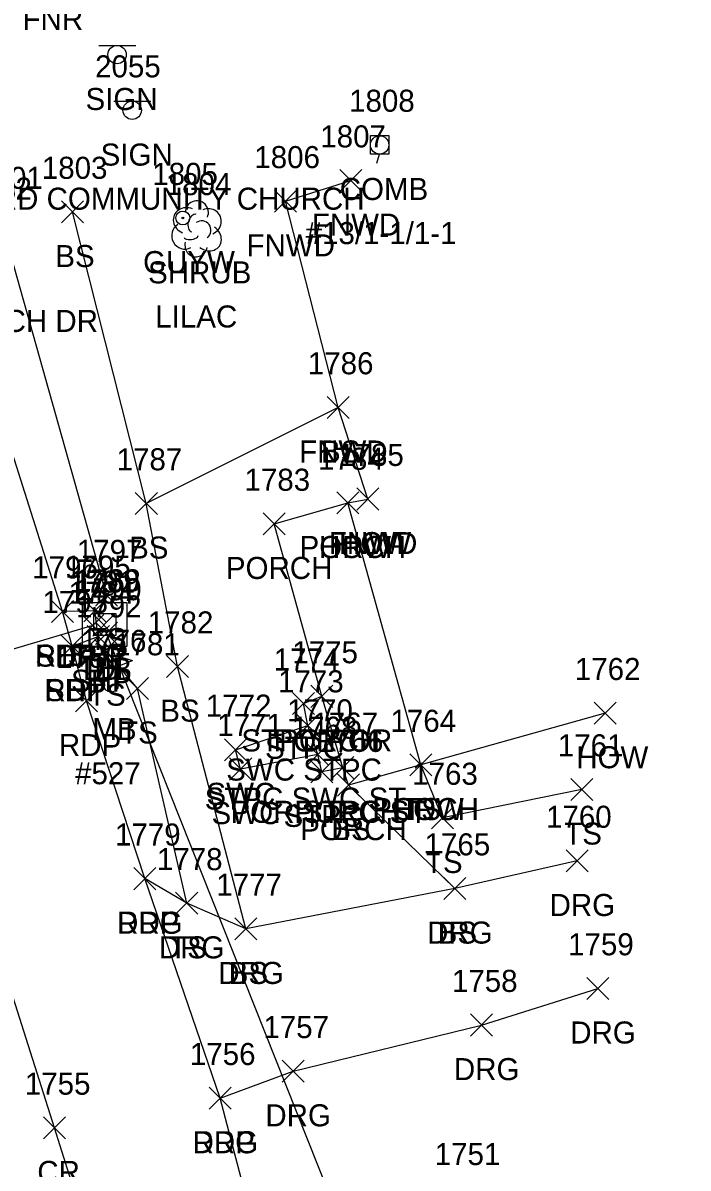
# Model space of a CAD drawing. Extents: x 1620157 to 1620595, y 115111 to 117885.
# Drawn here: x 1620291.9 to 1620352.1, y 115548.1 to 115651.9 of the extents above; entities that cross this region are included whole.
import ezdxf

# ---------------------------------------------------------------- set-up
doc = ezdxf.new("R2010")
doc.units = 0
for name, color, linetype in [('D_A', 7, 'Continuous'), ('D_I', 7, 'Continuous'), ('D_TIC', 7, 'Continuous'), ('DCP', 7, 'Continuous'), ('DS', 7, 'Continuous'), ('L_A', 7, 'Continuous'), ('L_C', 7, 'Continuous'), ('L_I', 7, 'Continuous'), ('L_TIC', 7, 'Continuous'), ('LBC', 7, 'Continuous'), ('LBF', 7, 'Continuous'), ('LELB', 7, 'Continuous'), ('LFNC', 7, 'Continuous'), ('LMB', 7, 'Continuous'), ('LSH', 7, 'Continuous'), ('P_A', 7, 'Continuous'), ('P_I', 7, 'Continuous'), ('P_TIC', 7, 'Continuous'), ('PET', 7, 'Continuous'), ('PRC', 7, 'Continuous'), ('PSP', 7, 'Continuous'), ('R_A', 7, 'Continuous'), ('R_I', 7, 'Continuous'), ('R_TIC', 7, 'Continuous'), ('RDG', 7, 'Continuous'), ('RSW', 7, 'Continuous'), ('S_A', 7, 'Continuous'), ('S_C', 7, 'Continuous'), ('S_I', 7, 'Continuous'), ('SSGN', 7, 'Continuous'), ('U_A', 7, 'Continuous'), ('U_C', 7, 'Continuous'), ('U_I', 7, 'Continuous'), ('UP', 7, 'Continuous'), ('UPGW', 7, 'Continuous')]:
    doc.layers.add(name, color=color, linetype=linetype)

msp = doc.modelspace()

# ---------------------------------------------------------------- linework, layer by layer
at = {"layer": 'D_TIC'}
for points in [[(1620297.2, 115596.27), (1620299.2, 115598.27)], [(1620299.2, 115596.27), (1620297.2, 115598.27)], [(1620298.19, 115596.33), (1620300.19, 115598.33)], [(1620300.19, 115596.33), (1620298.19, 115598.33)], [(1620298.44, 115595.57), (1620300.44, 115597.57)], [(1620300.44, 115595.57), (1620298.44, 115597.57)]]:
    msp.add_lwpolyline(points, dxfattribs=at)
at = {"layer": 'DCP'}
for points in [[(1620298.2, 115597.27), (1620266.48, 115587.84)], [(1620352.15, 115463.88), (1620299.44, 115596.57)]]:
    msp.add_lwpolyline(points, dxfattribs=at)
at = {"layer": 'DS'}
for p, q in [((1620297.27, 115599.38), (1620301.27, 115599.38)), ((1620297.27, 115595.38), (1620297.27, 115599.38)), ((1620301.27, 115599.38), (1620301.27, 115595.38)), ((1620298.27, 115596.38), (1620298.27, 115598.38)), ((1620298.27, 115598.38), (1620300.27, 115598.38)), ((1620300.27, 115598.38), (1620300.27, 115596.38)), ((1620299.28, 115597.38), (1620299.28, 115597.38)), ((1620299.28, 115597.38), (1620299.28, 115597.38)), ((1620300.27, 115596.38), (1620298.27, 115596.38)), ((1620301.27, 115595.38), (1620297.27, 115595.38))]:
    msp.add_line(p, q, dxfattribs=at)
at = {"layer": 'L_TIC'}
for points in [[(1620320.58, 115636.63), (1620322.58, 115638.63)], [(1620322.58, 115636.63), (1620320.58, 115638.63)], [(1620314.66, 115634.75), (1620316.66, 115636.75)], [(1620316.66, 115634.75), (1620314.66, 115636.75)], [(1620295.35, 115633.78), (1620297.35, 115635.78)], [(1620297.35, 115633.78), (1620295.35, 115635.78)], [(1620319.43, 115616.06), (1620321.43, 115618.06)], [(1620321.43, 115616.06), (1620319.43, 115618.06)], [(1620319.43, 115616.06), (1620321.43, 115618.06)], [(1620321.43, 115616.06), (1620319.43, 115618.06)], [(1620302.04, 115607.35), (1620304.04, 115609.35)], [(1620304.04, 115607.35), (1620302.04, 115609.35)], [(1620302.04, 115607.35), (1620304.04, 115609.35)], [(1620304.04, 115607.35), (1620302.04, 115609.35)], [(1620320.31, 115607.4), (1620322.31, 115609.4)], [(1620322.31, 115607.4), (1620320.31, 115609.4)], [(1620320.31, 115607.4), (1620322.31, 115609.4)], [(1620322.31, 115607.4), (1620320.31, 115609.4)], [(1620322.12, 115607.75), (1620324.12, 115609.75)], [(1620324.12, 115607.75), (1620322.12, 115609.75)], [(1620322.12, 115607.75), (1620324.12, 115609.75)], [(1620324.12, 115607.75), (1620322.12, 115609.75)], [(1620313.63, 115605.5), (1620315.63, 115607.5)], [(1620315.63, 115605.5), (1620313.63, 115607.5)], [(1620298.44, 115599.05), (1620300.44, 115601.05)], [(1620300.44, 115599.05), (1620298.44, 115601.05)], [(1620298.35, 115594.01), (1620300.35, 115596.01)], [(1620300.35, 115594.01), (1620298.35, 115596.01)], [(1620304.87, 115592.56), (1620306.87, 115594.56)], [(1620306.87, 115592.56), (1620304.87, 115594.56)], [(1620301.25, 115590.58), (1620303.25, 115592.58)], [(1620303.25, 115590.58), (1620301.25, 115592.58)], [(1620317.96, 115589.86), (1620319.96, 115591.86)], [(1620319.96, 115589.86), (1620317.96, 115591.86)], [(1620317.96, 115589.86), (1620319.96, 115591.86)], [(1620319.96, 115589.86), (1620317.96, 115591.86)], [(1620316.29, 115589.2), (1620318.29, 115591.2)], [(1620318.29, 115589.2), (1620316.29, 115591.2)], [(1620343.62, 115588.34), (1620345.62, 115590.34)], [(1620345.62, 115588.34), (1620343.62, 115590.34)], [(1620316.68, 115587.22), (1620318.68, 115589.22)], [(1620318.68, 115587.22), (1620316.68, 115589.22)], [(1620317.59, 115584.59), (1620319.59, 115586.59)], [(1620319.59, 115584.59), (1620317.59, 115586.59)], [(1620326.91, 115583.64), (1620328.91, 115585.64)], [(1620328.91, 115583.64), (1620326.91, 115585.64)], [(1620326.91, 115583.64), (1620328.91, 115585.64)], [(1620328.91, 115583.64), (1620326.91, 115585.64)], [(1620326.91, 115583.64), (1620328.91, 115585.64)], [(1620328.91, 115583.64), (1620326.91, 115585.64)], [(1620317.96, 115583.02), (1620319.96, 115585.02)], [(1620319.96, 115583.02), (1620317.96, 115585.02)], [(1620319.84, 115583.39), (1620321.84, 115585.39)], [(1620321.84, 115583.39), (1620319.84, 115585.39)], [(1620319.84, 115583.39), (1620321.84, 115585.39)], [(1620321.84, 115583.39), (1620319.84, 115585.39)], [(1620320.37, 115581.82), (1620322.37, 115583.82)], [(1620322.37, 115581.82), (1620320.37, 115583.82)], [(1620320.37, 115581.82), (1620322.37, 115583.82)], [(1620322.37, 115581.82), (1620320.37, 115583.82)], [(1620341.51, 115581.42), (1620343.51, 115583.42)], [(1620343.51, 115581.42), (1620341.51, 115583.42)], [(1620328.88, 115578.84), (1620330.88, 115580.84)], [(1620330.88, 115578.84), (1620328.88, 115580.84)], [(1620330, 115572.44), (1620332, 115574.44)], [(1620332, 115572.44), (1620330, 115574.44)], [(1620305.7, 115571.1), (1620307.7, 115573.1)], [(1620307.7, 115571.1), (1620305.7, 115573.1)], [(1620311.07, 115568.78), (1620313.07, 115570.78)], [(1620313.07, 115568.78), (1620311.07, 115570.78)]]:
    msp.add_lwpolyline(points, dxfattribs=at)
at = {"layer": 'LBC'}
msp.add_lwpolyline([(1620344.62, 115589.34), (1620327.91, 115584.64), (1620321.31, 115608.4), (1620323.12, 115608.75)], dxfattribs=at)
at = {"layer": 'LBF'}
for points in [[(1620327.91, 115584.64), (1620321.37, 115582.82), (1620320.84, 115584.39), (1620318.96, 115590.86), (1620314.63, 115606.5), (1620321.31, 115608.4)], [(1620320.84, 115584.39), (1620318.96, 115584.02), (1620318.59, 115585.59), (1620317.68, 115588.22), (1620317.29, 115590.2), (1620318.96, 115590.86)]]:
    msp.add_lwpolyline(points, dxfattribs=at)
at = {"layer": 'LELB'}
for points in [[(1620299.44, 115600.05), (1620289.92, 115633.87), (1620283.73, 115653.38)], [(1620312.07, 115569.78), (1620305.87, 115593.56), (1620303.04, 115608.35), (1620296.35, 115634.78)], [(1620320.43, 115617.06), (1620303.04, 115608.35)], [(1620306.7, 115572.1), (1620302.25, 115591.58), (1620299.35, 115595.01)], [(1620342.51, 115582.42), (1620329.88, 115579.84), (1620327.91, 115584.64)], [(1620331, 115573.44), (1620321.37, 115582.82)]]:
    msp.add_lwpolyline(points, dxfattribs=at)
at = {"layer": 'LFNC'}
msp.add_lwpolyline([(1620323.12, 115608.75), (1620320.43, 115617.06), (1620315.66, 115635.75), (1620321.58, 115637.63)], dxfattribs=at)
at = {"layer": 'LMB'}
for p, q in [((1620300.49, 115594.49), (1620301.79, 115594.11)), ((1620300.5, 115591.9), (1620300.5, 115594.49)), ((1620300.5, 115593.59), (1620301.78, 115594.1)), ((1620299.84, 115591.89), (1620299.84, 115591.89))]:
    msp.add_line(p, q, dxfattribs=at)
msp.add_circle((1620299.84, 115591.89), 0.656, dxfattribs=at)
at = {"layer": 'LSH'}
msp.add_line((1620307.57, 115633.3), (1620307.57, 115633.3), dxfattribs=at)
msp.add_line((1620307.57, 115633.3), (1620307.57, 115633.3), dxfattribs=at)
msp.add_arc((1620307.62, 115634.74), 1.05, 335.5272, 180.9563, dxfattribs=at)
for centre, major_axis, ratio, start_param, end_param in [((1620306.78, 115633.97), (1.21, -0.51), 0.895232, 1.570796, 4.712389), ((1620307.36, 115633.76), (-0.208, -0.792), 0.645439, 3.141593, 6.283185), ((1620308.61, 115633.89), (-1.14, -0.48), 0.949671, 1.570796, 4.712389), ((1620306.49, 115632.59), (0.58, -1.04), 0.959034, 3.141593, 6.283185), ((1620308.07, 115633.14), (-0.5, 0.667), 0.989748, 3.141593, 6.283185), ((1620308.57, 115632.47), (-1.09, 0.79), 0.841452, 1.570796, 4.712389), ((1620307.11, 115632.55), (-0.625, -0.083), 0.423636, 0, 3.141593), ((1620307.57, 115631.8), (0.26, 1.06), 0.942809, 1.570796, 4.712389)]:
    msp.add_ellipse(centre, major_axis=major_axis, ratio=ratio, start_param=start_param, end_param=end_param, dxfattribs=at)
at = {"layer": 'P_TIC'}
for points in [[(1620294.45, 115597.55), (1620296.45, 115599.55)], [(1620296.45, 115597.55), (1620294.45, 115599.55)], [(1620294.45, 115597.55), (1620296.45, 115599.55)], [(1620296.45, 115597.55), (1620294.45, 115599.55)], [(1620297.37, 115597.62), (1620299.37, 115599.62)], [(1620299.37, 115597.62), (1620297.37, 115599.62)], [(1620297.69, 115595.27), (1620299.69, 115597.27)], [(1620299.69, 115595.27), (1620297.69, 115597.27)], [(1620295.31, 115594.42), (1620297.31, 115596.42)], [(1620297.31, 115594.42), (1620295.31, 115596.42)], [(1620295.31, 115594.42), (1620297.31, 115596.42)], [(1620297.31, 115594.42), (1620295.31, 115596.42)], [(1620296.63, 115589.44), (1620298.63, 115591.44)], [(1620298.63, 115589.44), (1620296.63, 115591.44)], [(1620301.9, 115573.33), (1620303.9, 115575.33)], [(1620303.9, 115573.33), (1620301.9, 115575.33)], [(1620308.74, 115553.43), (1620310.74, 115555.43)], [(1620310.74, 115553.43), (1620308.74, 115555.43)], [(1620293.72, 115550.74), (1620295.72, 115552.74)], [(1620295.72, 115550.74), (1620293.72, 115552.74)]]:
    msp.add_lwpolyline(points, dxfattribs=at)
at = {"layer": 'PET'}
msp.add_lwpolyline([(1620336.22, 115456.8), (1620332.52, 115469.32), (1620324.59, 115500.95), (1620318.09, 115527.23), (1620313.06, 115541.76), (1620309.74, 115554.43), (1620302.9, 115574.33), (1620297.63, 115590.44), (1620296.31, 115595.42), (1620295.45, 115598.55), (1620285.02, 115631.41), (1620284, 115634.58), (1620271.05, 115676.55), (1620263.94, 115701.46), (1620257.2, 115724.05), (1620247.86, 115755.87), (1620237.56, 115791.5), (1620229.87, 115820.37), (1620222.52, 115845.46)], dxfattribs=at)
at = {"layer": 'PRC'}
msp.add_lwpolyline([(1620328.08, 115447.46), (1620322.14, 115466.61), (1620311.32, 115499.81), (1620303.78, 115522.91), (1620294.72, 115551.74), (1620279.31, 115600.23), (1620271.12, 115626.45), (1620257.91, 115669.49), (1620247.64, 115703.03), (1620242.45, 115719.65), (1620232.98, 115752.35), (1620223.66, 115784.04), (1620214.14, 115816.15), (1620207.47, 115841.18)], dxfattribs=at)
at = {"layer": 'PSP'}
msp.add_lwpolyline([(1620296.31, 115595.42), (1620298.69, 115596.27), (1620298.37, 115598.62), (1620295.45, 115598.55)], dxfattribs=at)
at = {"layer": 'R_TIC'}
for points in [[(1620316.68, 115587.22), (1620318.68, 115589.22)], [(1620318.68, 115587.22), (1620316.68, 115589.22)], [(1620310.13, 115585.02), (1620312.13, 115587.02)], [(1620312.13, 115585.02), (1620310.13, 115587.02)], [(1620317.59, 115584.59), (1620319.59, 115586.59)], [(1620319.59, 115584.59), (1620317.59, 115586.59)], [(1620310.59, 115583.27), (1620312.59, 115585.27)], [(1620312.59, 115583.27), (1620310.59, 115585.27)], [(1620341.1, 115574.94), (1620343.1, 115576.94)], [(1620343.1, 115574.94), (1620341.1, 115576.94)], [(1620301.9, 115573.33), (1620303.9, 115575.33)], [(1620303.9, 115573.33), (1620301.9, 115575.33)], [(1620330, 115572.44), (1620332, 115574.44)], [(1620332, 115572.44), (1620330, 115574.44)], [(1620305.7, 115571.1), (1620307.7, 115573.1)], [(1620307.7, 115571.1), (1620305.7, 115573.1)], [(1620311.07, 115568.78), (1620313.07, 115570.78)], [(1620313.07, 115568.78), (1620311.07, 115570.78)], [(1620342.97, 115563.38), (1620344.97, 115565.38)], [(1620344.97, 115563.38), (1620342.97, 115565.38)], [(1620332.43, 115560.06), (1620334.43, 115562.06)], [(1620334.43, 115560.06), (1620332.43, 115562.06)], [(1620315.34, 115555.87), (1620317.34, 115557.87)], [(1620317.34, 115555.87), (1620315.34, 115557.87)], [(1620308.74, 115553.43), (1620310.74, 115555.43)], [(1620310.74, 115553.43), (1620308.74, 115555.43)]]:
    msp.add_lwpolyline(points, dxfattribs=at)
at = {"layer": 'RDG'}
for points in [[(1620342.1, 115575.94), (1620331, 115573.44), (1620312.07, 115569.78), (1620306.7, 115572.1), (1620302.9, 115574.33)], [(1620309.74, 115554.43), (1620316.34, 115556.87), (1620333.43, 115561.06), (1620343.97, 115564.38)]]:
    msp.add_lwpolyline(points, dxfattribs=at)
at = {"layer": 'RSW'}
msp.add_lwpolyline([(1620318.59, 115585.59), (1620311.59, 115584.27), (1620311.13, 115586.02), (1620317.68, 115588.22)], dxfattribs=at)
at = {"layer": 'SSGN'}
for p, q in [((1620298.74, 115649.88), (1620302.08, 115649.88)), ((1620300.39, 115649.04), (1620300.39, 115649.04)), ((1620300.11, 115644.83), (1620303.45, 115644.83)), ((1620301.76, 115644), (1620301.76, 115644))]:
    msp.add_line(p, q, dxfattribs=at)
for centre in [(1620300.39, 115649.04), (1620301.76, 115644)]:
    msp.add_circle(centre, 0.833, dxfattribs=at)
at = {"layer": 'UP'}
for p, q in [((1620323.36, 115640.03), (1620323.36, 115641.7)), ((1620323.36, 115641.7), (1620325.02, 115641.7)), ((1620324.44, 115642.53), (1620324.19, 115641.7)), ((1620325.02, 115641.7), (1620325.02, 115640.03)), ((1620324.19, 115640.86), (1620324.19, 115640.86)), ((1620325.02, 115640.03), (1620323.36, 115640.03)), ((1620323.94, 115639.2), (1620324.19, 115640.03))]:
    msp.add_line(p, q, dxfattribs=at)
msp.add_circle((1620324.19, 115640.86), 0.833, dxfattribs=at)
at = {"layer": 'UPGW'}
for radius in [0.625, 0.0833]:
    msp.add_circle((1620306.35, 115634.23), radius, dxfattribs=at)

# ---------------------------------------------------------------- texts
at = {"layer": 'D_A'}
for s, p in [('DIB', (1620297.29, 115592.33)), ('P', (1620297.58, 115592.27)), ('DI', (1620298.33, 115592.38)), ('P', (1620298.82, 115591.57))]:
    msp.add_text(s, height=2, dxfattribs=at).set_placement(p)
at = {"layer": 'D_I'}
for s, p in [('1791', (1620296.08, 115600.27)), ('1789', (1620296.49, 115600.33)), ('1788', (1620296.59, 115600.38)), ('1790', (1620296.66, 115599.57))]:
    msp.add_text(s, height=2, dxfattribs=at).set_placement(p)
at = {"layer": 'L_A'}
for s, p in [('FNR', (1620291.82, 115651.29)), ('FNWD', (1620318.04, 115632.63)), ('FNWD', (1620312.12, 115630.75)), ('BS', (1620294.79, 115629.78)), ('SHRUB', (1620303.2, 115628.3)), ('FNWD', (1620316.89, 115612.06)), ('BS', (1620318.87, 115612.06)), ('BS', (1620301.48, 115603.35)), ('BS', (1620301.48, 115603.35)), ('PORCH', (1620316.93, 115603.4)), ('HOW', (1620318.69, 115603.4)), ('FNWD', (1620319.59, 115603.75)), ('HOW', (1620320.51, 115603.75)), ('PORCH', (1620310.25, 115601.5)), ('TS', (1620297.85, 115595.05)), ('TS', (1620297.76, 115590.01)), ('BS', (1620304.31, 115588.56)), ('MB', (1620298.15, 115586.89)), ('TS', (1620300.66, 115586.58)), ('STPC POR', (1620311.66, 115585.86)), ('PORCH', (1620314.58, 115585.86)), ('STPC', (1620313.8, 115585.2)), ('HOW', (1620342.01, 115584.34)), ('SWC STPC', (1620310.28, 115583.22)), ('STPC SWC ST', (1620308.33, 115580.59)), ('POR STPC ST', (1620310.68, 115579.39)), ('PORCH', (1620316.46, 115579.39)), ('PORCH', (1620323.53, 115579.64)), ('HOW', (1620325.29, 115579.64)), ('TS', (1620326.32, 115579.64)), ('STPC', (1620315.48, 115579.02)), ('PORCH', (1620316.99, 115577.82)), ('BS', (1620319.81, 115577.82)), ('TS', (1620340.92, 115577.42)), ('TS', (1620328.29, 115574.84)), ('BS', (1620329.45, 115568.44)), ('TS', (1620305.11, 115567.1)), ('BS', (1620310.51, 115564.78))]:
    msp.add_text(s, height=2, dxfattribs=at).set_placement(p)
at = {"layer": 'L_C'}
for s, p in [('38 CHURCH DR', (1620278.75, 115623.9)), ('LILAC', (1620303.85, 115624.3)), ('#527', (1620296.58, 115582.89))]:
    msp.add_text(s, height=2, dxfattribs=at).set_placement(p)
at = {"layer": 'L_I'}
for s, p in [('1807', (1620318.81, 115640.63)), ('1806', (1620312.83, 115638.75)), ('1803', (1620293.57, 115637.78)), ('1801', (1620287.71, 115636.87)), ('1802', (1620286.72, 115635.9)), ('1804', (1620304.8, 115636.3)), ('1786', (1620317.68, 115620.06)), ('1786', (1620317.68, 115620.06)), ('1785', (1620320.43, 115611.75)), ('1785', (1620320.43, 115611.75)), ('1787', (1620300.35, 115611.35)), ('1787', (1620300.35, 115611.35)), ('1784', (1620318.61, 115611.4)), ('1784', (1620318.61, 115611.4)), ('1783', (1620311.94, 115609.5)), ('1797', (1620296.74, 115603.05)), ('1792', (1620296.66, 115598.01)), ('1782', (1620303.17, 115596.56)), ('1776', (1620297.1, 115594.89)), ('1781', (1620300.12, 115594.58)), ('1775', (1620316.27, 115593.86)), ('1775', (1620316.27, 115593.86)), ('1774', (1620314.59, 115593.2)), ('1762', (1620341.88, 115592.34)), ('1773', (1620314.98, 115591.22)), ('1770', (1620315.81, 115588.59)), ('1764', (1620325.17, 115587.64)), ('1764', (1620325.17, 115587.64)), ('1764', (1620325.17, 115587.64)), ('1768', (1620316.22, 115587.02)), ('1767', (1620318.1, 115587.39)), ('1767', (1620318.1, 115587.39)), ('1766', (1620318.58, 115585.82)), ('1766', (1620318.58, 115585.82)), ('1761', (1620340.34, 115585.42)), ('1763', (1620327.14, 115582.84)), ('1765', (1620328.26, 115576.44)), ('1778', (1620304, 115575.1)), ('1777', (1620309.38, 115572.78)), ('1751', (1620329.18, 115548.36))]:
    msp.add_text(s, height=2, dxfattribs=at).set_placement(p)
at = {"layer": 'P_A'}
for s, p in [('SHP', (1620292.98, 115593.55)), ('RDP', (1620292.93, 115593.55)), ('SHP', (1620295.91, 115593.62)), ('SHP', (1620296.22, 115591.27)), ('SHP', (1620293.85, 115590.42)), ('RDP', (1620293.8, 115590.42)), ('RDP', (1620295.12, 115585.44)), ('RDP', (1620300.39, 115569.33)), ('RDP', (1620307.23, 115549.43)), ('CR', (1620293.16, 115546.74))]:
    msp.add_text(s, height=2, dxfattribs=at).set_placement(p)
at = {"layer": 'P_I'}
for s, p in [('1796', (1620292.7, 115601.55)), ('1796', (1620292.7, 115601.55)), ('1795', (1620295.68, 115601.62)), ('1794', (1620296, 115599.27)), ('1793', (1620293.62, 115598.42)), ('1793', (1620293.62, 115598.42)), ('1780', (1620294.85, 115593.44)), ('1779', (1620300.2, 115577.33)), ('1756', (1620306.99, 115557.43)), ('1755', (1620292.03, 115554.74))]:
    msp.add_text(s, height=2, dxfattribs=at).set_placement(p)
at = {"layer": 'R_A'}
for s, p in [('SWC STPC', (1620310.28, 115583.22)), ('STPC SWC ST', (1620308.33, 115580.59)), ('SWC', (1620308.49, 115581.02)), ('SWC', (1620308.95, 115579.27)), ('DRG', (1620339.59, 115570.94)), ('DRG', (1620300.39, 115569.33)), ('DRG', (1620328.49, 115568.44)), ('DRG', (1620304.18, 115567.1)), ('DRG', (1620309.56, 115564.78)), ('DRG', (1620341.46, 115559.38)), ('DRG', (1620330.92, 115556.06)), ('DRG', (1620313.83, 115551.87)), ('DRG', (1620307.23, 115549.43))]:
    msp.add_text(s, height=2, dxfattribs=at).set_placement(p)
at = {"layer": 'R_I'}
for s, p in [('1773', (1620314.98, 115591.22)), ('1772', (1620308.43, 115589.02)), ('1770', (1620315.81, 115588.59)), ('1771', (1620309.47, 115587.27)), ('1760', (1620339.27, 115578.94)), ('1779', (1620300.2, 115577.33)), ('1765', (1620328.26, 115576.44)), ('1778', (1620304, 115575.1)), ('1777', (1620309.38, 115572.78)), ('1759', (1620341.27, 115567.38)), ('1758', (1620330.74, 115564.06)), ('1757', (1620313.65, 115559.87)), ('1756', (1620306.99, 115557.43))]:
    msp.add_text(s, height=2, dxfattribs=at).set_placement(p)
at = {"layer": 'S_A'}
for p in [(1620297.53, 115644.02), (1620298.9, 115638.98)]:
    msp.add_text('SIGN', height=2, dxfattribs=at).set_placement(p)
at = {"layer": 'S_C'}
msp.add_text('GUILFORD COMMUNITY CHURCH', height=2, dxfattribs=at).set_placement((1620279.44, 115634.98))
at = {"layer": 'S_I'}
msp.add_text('2055', height=2, dxfattribs=at).set_placement((1620298.4, 115646.98))
at = {"layer": 'U_A'}
for s, p in [('COMB', (1620320.57, 115635.86)), ('GUYW', (1620302.75, 115629.23))]:
    msp.add_text(s, height=2, dxfattribs=at).set_placement(p)
at = {"layer": 'U_C'}
msp.add_text('#13/1-1/1-1', height=2, dxfattribs=at).set_placement((1620317.48, 115631.86))
at = {"layer": 'U_I'}
for s, p in [('1808', (1620321.42, 115643.86)), ('1805', (1620303.58, 115637.23))]:
    msp.add_text(s, height=2, dxfattribs=at).set_placement(p)

doc.saveas('drawing.dxf')
